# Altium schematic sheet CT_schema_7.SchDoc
size 274 x 160 mm
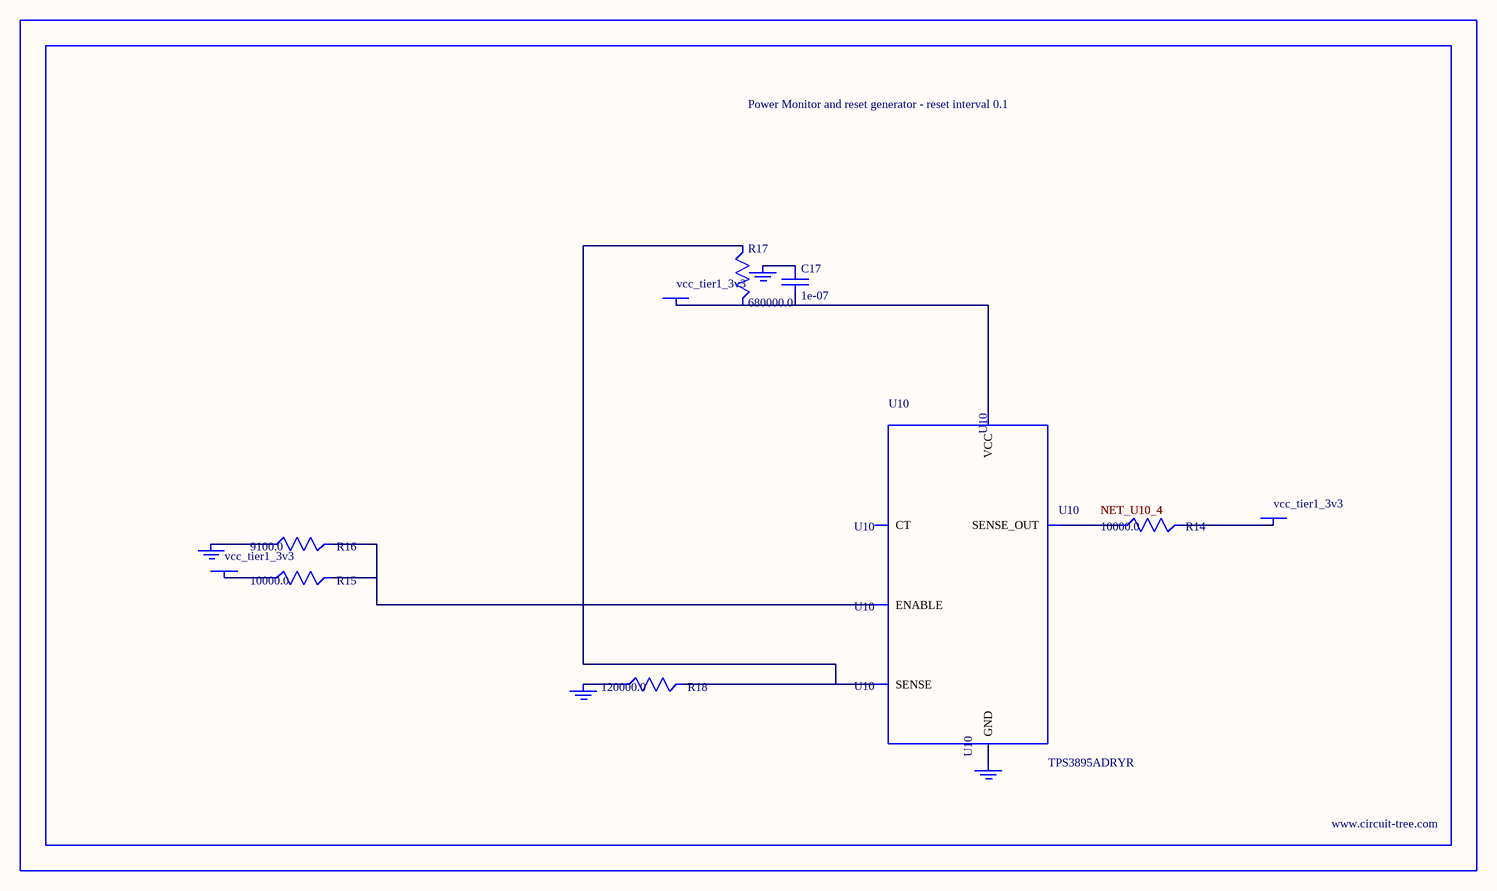
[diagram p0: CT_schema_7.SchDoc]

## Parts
BORDER6  (no value)
C17  1e-07  [C0402]
GND_INSTANCE_6_0  (no value)
GND_INSTANCE_6_1  (no value)
GND_INSTANCE_6_2  (no value)
GND_INSTANCE_6_3  (no value)
POWER_INSTANCE_6_0  vcc_tier1_3v3
POWER_INSTANCE_6_1  vcc_tier1_3v3
POWER_INSTANCE_6_2  vcc_tier1_3v3
R14  10000.0  [R0603]
R15  10000.0  [R0603]
R16  9100.0  [R0603]
R17  680000.0  [R0603]
R18  120000.0  [R0603]
U10  TPS3895ADRYR  [SON-6]

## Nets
NetC17_1: C17.1 GND_INSTANCE_6_2.0(GND)
NetC17_2: C17.2 POWER_INSTANCE_6_2.0(PWR) R17.2 U10.6(VCC)
NetGND_INSTANCE_6_0_0: GND_INSTANCE_6_0.0(GND) R16.1
NetGND_INSTANCE_6_1_0: GND_INSTANCE_6_1.0(GND) R18.1
NetGND_INSTANCE_6_3_0: GND_INSTANCE_6_3.0(GND) U10.2(GND)
NetPOWER_INSTANCE_6_0_0: POWER_INSTANCE_6_0.0(PWR) R15.1
NetPOWER_INSTANCE_6_1_0: POWER_INSTANCE_6_1.0(PWR) R14.2
NetR14_1: R14.1 U10.4(SENSE_OUT)
NetR15_2: R15.2 R16.2 U10.1(ENABLE)
NetR17_1: R17.1 R18.2 U10.3(SENSE)

Not connected (* = marked no-connect by the designer): U10 5(CT)

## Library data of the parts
BORDER6 = BORDER_PAGE6
C17 = C0402C104K3RACTU
GND_INSTANCE_6_0-GND_INSTANCE_6_3 = GND
POWER_INSTANCE_6_0-POWER_INSTANCE_6_2 = PWR
R14 R15 = RC0603JR-0710KL
R16 = RC0603JR-079K1L
R17 = RC0603JR-07680KL
R18 = RC0603JR-07120KL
